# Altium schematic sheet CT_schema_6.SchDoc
size 277 x 170 mm
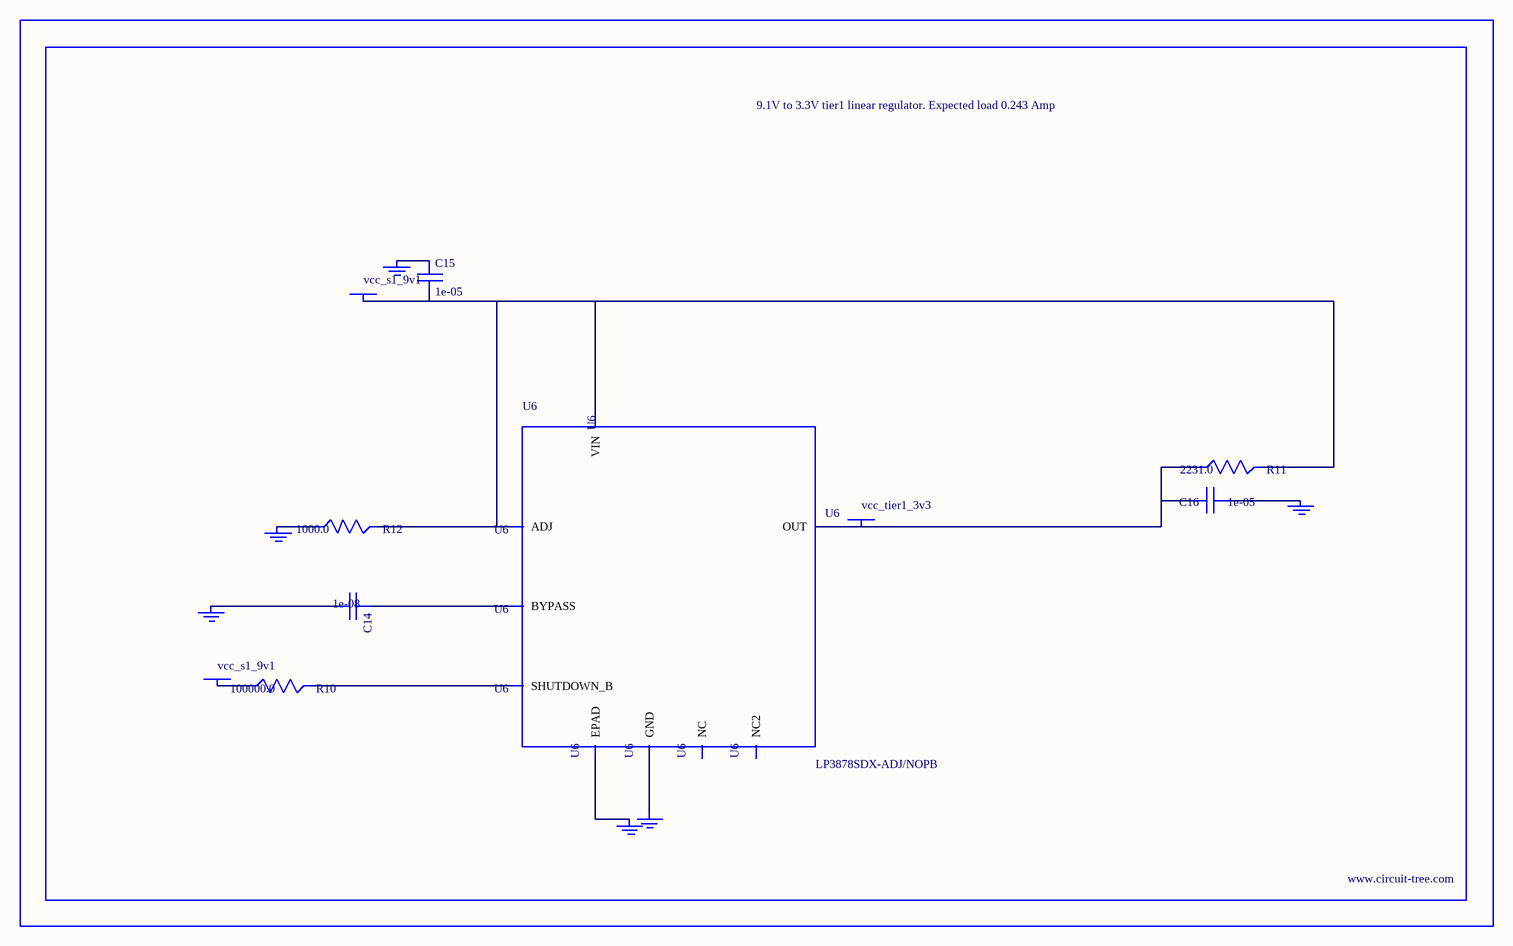
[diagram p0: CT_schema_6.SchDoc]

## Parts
BORDER5  (no value)
C14  1e-08  [C0402]
C15  1e-05  [C1206]
C16  1e-05  [C1210]
GND_INSTANCE_5_0  (no value)
GND_INSTANCE_5_1  (no value)
GND_INSTANCE_5_2  (no value)
GND_INSTANCE_5_3  (no value)
GND_INSTANCE_5_4  (no value)
GND_INSTANCE_5_5  (no value)
POWER_INSTANCE_5_0  vcc_s1_9v1
POWER_INSTANCE_5_1  vcc_s1_9v1
POWER_INSTANCE_5_2  vcc_tier1_3v3
R10  100000.0  [R0603]
R11  2231.0  [R0603]
R12  1000.0  [R0603]
U6  LP3878SDX-ADJ/NOPB  [WSON-8]

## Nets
NetC14_1: C14.1 U6.1(BYPASS)
NetC14_2: C14.2 GND_INSTANCE_5_0.0(GND)
NetC15_1: C15.1 GND_INSTANCE_5_1.0(GND)
NetC15_2: C15.2 POWER_INSTANCE_5_0.0(PWR) R11.2 R12.2 U6.4(VIN) U6.6(ADJ)
NetC16_1: C16.1 GND_INSTANCE_5_2.0(GND)
NetC16_2: C16.2 POWER_INSTANCE_5_2.0(PWR) R11.1 U6.5(OUT)
NetGND_INSTANCE_5_3_0: GND_INSTANCE_5_3.0(GND) R12.1
NetGND_INSTANCE_5_4_0: GND_INSTANCE_5_4.0(GND) U6.PAD(EPAD)
NetGND_INSTANCE_5_5_0: GND_INSTANCE_5_5.0(GND) U6.3(GND)
NetPOWER_INSTANCE_5_1_0: POWER_INSTANCE_5_1.0(PWR) R10.1
NetR10_2: R10.2 U6.8(SHUTDOWN_B)

Not connected (* = marked no-connect by the designer): U6 2(NC) 7(NC2)

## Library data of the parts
BORDER5 = BORDER_PAGE5
C14 = C0402C103K3RAC
C15 = C1206C106K3RACTU
C16 = GRM32DR61E106MA12L
GND_INSTANCE_5_0-GND_INSTANCE_5_5 = GND
POWER_INSTANCE_5_0-POWER_INSTANCE_5_2 = PWR
R10 = RC0603JR-07100KL
R11 = R11
R12 = RC0603JR-071KL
